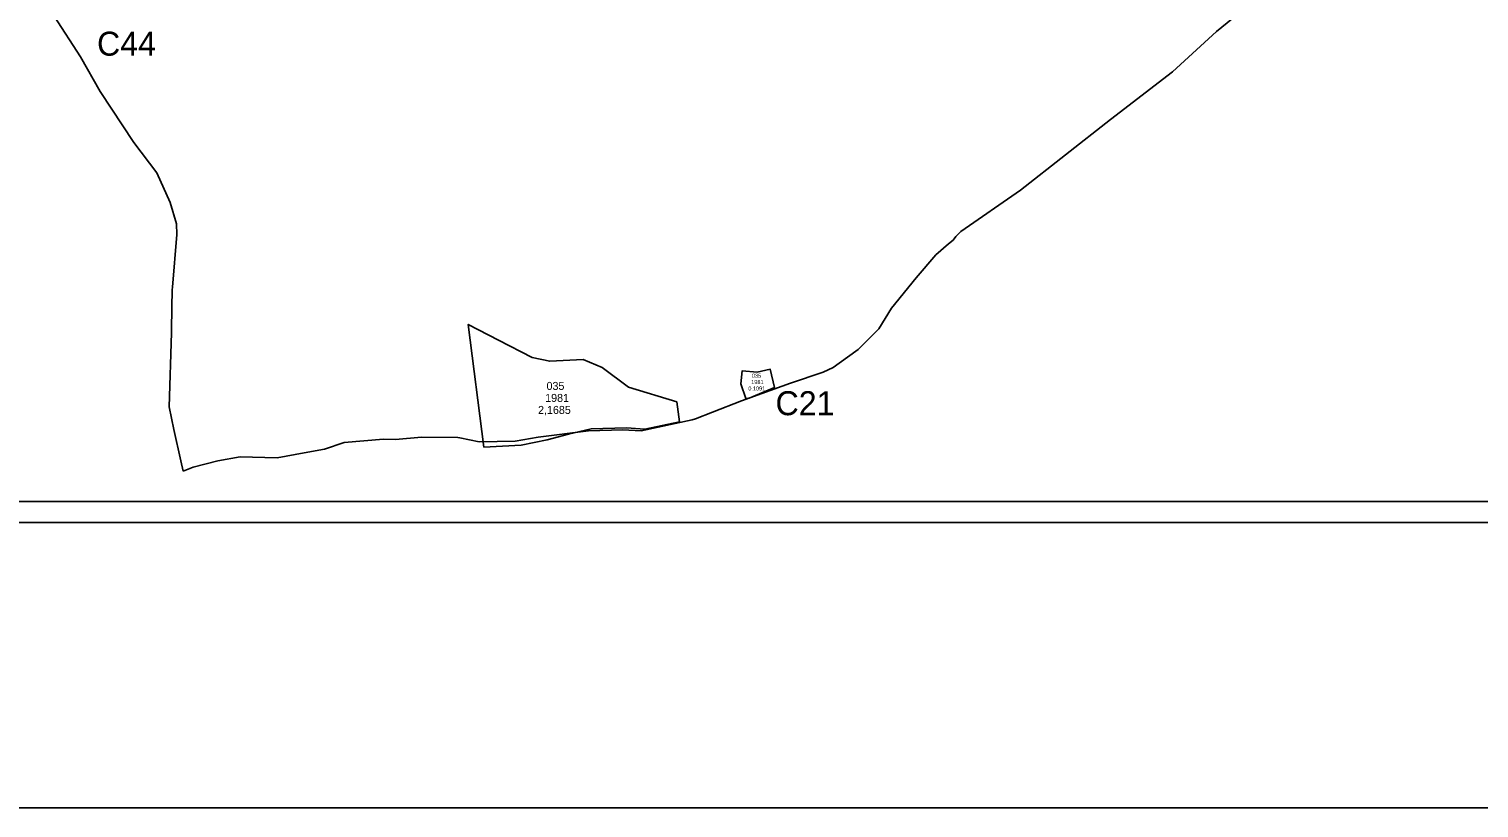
# Model space of a CAD drawing. Extents: x -557103 to -548162, y -1041918 to -1033974.
# Drawn here: x -554022 to -552210, y -1040019 to -1039045 of the extents above; entities that cross this region are included whole.
import ezdxf

# ---------------------------------------------------------------- set-up
doc = ezdxf.new("R2010")
doc.units = 0
for name, color, linetype in [('body1', 7, 'Continuous'), ('body3', 7, 'Continuous'), ('Rámeček', 7, 'Continuous'), ('Vrstva 37', 7, 'Continuous'), ('Vrstva 63', 7, 'Continuous'), ('Vrstva 9', 7, 'Continuous')]:
    doc.layers.add(name, color=color, linetype=linetype)

msp = doc.modelspace()

# ---------------------------------------------------------------- linework, layer by layer
at = {"layer": 'body1'}
msp.add_lwpolyline([(-550469.3, -1040018.6), (-555211.6, -1040018.6), (-555211.6, -1034654.7), (-550469.3, -1034654.7)], close=True, dxfattribs=at)
at = {"layer": 'body3'}
for p, q in [((-552537.9, -1039048.6), (-552497.9, -1039016.2)), ((-553990.6, -1039029.5), (-553957.8, -1039080.2)), ((-552593.2, -1039098.7), (-552537.9, -1039048.6)), ((-553957.8, -1039080.2), (-553932.9, -1039123.5)), ((-552670.5, -1039158.6), (-552593.2, -1039098.7)), ((-553932.9, -1039123.5), (-553891.2, -1039187.1)), ((-552783, -1039246.6), (-552670.5, -1039158.6)), ((-553891.2, -1039187.1), (-553862.3, -1039225.1)), ((-553862.3, -1039225.1), (-553845.6, -1039262.2)), ((-552857.7, -1039298.3), (-552783, -1039246.6)), ((-553845.6, -1039262.2), (-553837.6, -1039288.8)), ((-553837.6, -1039288.8), (-553837.4, -1039302.1)), ((-553837.4, -1039302.1), (-553842.9, -1039367.8)), ((-552873, -1039313.9), (-552867.3, -1039309.4)), ((-552867.3, -1039309.4), (-552863.8, -1039304.7)), ((-552863.8, -1039304.7), (-552857.7, -1039298.3)), ((-552913.4, -1039356.4), (-552888.8, -1039327.5)), ((-552888.8, -1039327.5), (-552873, -1039313.9)), ((-552944.4, -1039394.3), (-552913.4, -1039356.4)), ((-553843.4, -1039384.2), (-553843.6, -1039387.8)), ((-553843.1, -1039380.4), (-553843.4, -1039384.2)), ((-553842.9, -1039367.8), (-553843.2, -1039371.1)), ((-553843.2, -1039371.1), (-553843.2, -1039373.3)), ((-553843.2, -1039373.3), (-553843.1, -1039377.3)), ((-553843.1, -1039377.3), (-553843.1, -1039380.4)), ((-553843.7, -1039390.3), (-553844.1, -1039424.8)), ((-553843.6, -1039387.8), (-553843.7, -1039390.3)), ((-552960, -1039419.9), (-552944.4, -1039394.3)), ((-552985.9, -1039446), (-552960, -1039419.9)), ((-553844.1, -1039424.8), (-553846.8, -1039517.3)), ((-553017.3, -1039468.1), (-552999.4, -1039455.4)), ((-552999.4, -1039455.4), (-552985.9, -1039446)), ((-553070.4, -1039487.7), (-553029.7, -1039474.1)), ((-553029.7, -1039474.1), (-553017.3, -1039468.1)), ((-553131.7, -1039510.1), (-553070.4, -1039487.7)), ((-553167.7, -1039524.2), (-553131.7, -1039510.1)), ((-553846.8, -1039517.3), (-553841.1, -1039545.9)), ((-553189.2, -1039532.4), (-553167.7, -1039524.2)), ((-553841.1, -1039545.9), (-553832.2, -1039584.8)), ((-553385.8, -1039555.5), (-553322.8, -1039547.5)), ((-553322.8, -1039547.5), (-553279.9, -1039546.2)), ((-553279.9, -1039546.2), (-553257.2, -1039547.3)), ((-553257.2, -1039547.3), (-553193.2, -1039533.8)), ((-553193.2, -1039533.8), (-553189.2, -1039532.4)), ((-553652.8, -1039570.2), (-553628.1, -1039562.1)), ((-553628.1, -1039562.1), (-553579.1, -1039557.7)), ((-553579.1, -1039557.7), (-553564.1, -1039558.3)), ((-553564.1, -1039558.3), (-553531.4, -1039555.3)), ((-553531.4, -1039555.3), (-553486.2, -1039555.6)), ((-553486.2, -1039555.6), (-553483.7, -1039556.1)), ((-553483.7, -1039556.1), (-553459.3, -1039561)), ((-553459.3, -1039561), (-553414.7, -1039560.5)), ((-553414.7, -1039560.5), (-553385.8, -1039555.5)), ((-553785.9, -1039584.8), (-553758.1, -1039579.9)), ((-553758.1, -1039579.9), (-553712, -1039581.2)), ((-553712, -1039581.2), (-553678.2, -1039575)), ((-553678.2, -1039575), (-553652.8, -1039570.2)), ((-553832.2, -1039584.8), (-553829.3, -1039597.6)), ((-553829.3, -1039597.6), (-553817, -1039592.7)), ((-553817, -1039592.7), (-553785.9, -1039584.8))]:
    msp.add_line(p, q, dxfattribs=at)
at = {"layer": 'Rámeček'}
for points in [[(-555307.9, -1039662.1), (-550042, -1039662.1), (-550042, -1034604.4), (-555307.9, -1034604.4)], [(-555307.9, -1034604.4), (-548161.9, -1034604.4), (-548161.9, -1039661.8), (-555307.9, -1039661.8)]]:
    msp.add_lwpolyline(points, close=True, dxfattribs=at)
at = {"layer": 'Vrstva 63'}
msp.add_lwpolyline([(-550519.3, -1039635.9), (-556362.3, -1039635.9), (-556362.3, -1034682.3), (-550519.3, -1034682.3)], close=True, dxfattribs=at)
at = {"layer": 'Vrstva 9'}
for points in [[(-553453.8, -1039567.7), (-553473.1, -1039414.4), (-553435.4, -1039434.3), (-553393.4, -1039455.6), (-553371.2, -1039460.5), (-553329.6, -1039458.2), (-553305.7, -1039468.3), (-553272.8, -1039493), (-553212.5, -1039511.2), (-553209.3, -1039536.2), (-553252.5, -1039545.2), (-553275.5, -1039543.8), (-553319.5, -1039545), (-553348, -1039551.4), (-553374.6, -1039558.7), (-553407.2, -1039565.5)], [(-553126.2, -1039507), (-553132.7, -1039488.6), (-553130.7, -1039472.4), (-553112.1, -1039474.3), (-553095.8, -1039470.4), (-553090.4, -1039493.2), (-553122.2, -1039506.6)]]:
    msp.add_lwpolyline(points, close=True, dxfattribs=at)

# ---------------------------------------------------------------- texts
at = {"layer": 'Vrstva 37'}
for s, p in [('C44', (-553937, -1039078.7)), ('C21', (-553089.1, -1039527.9))]:
    msp.add_text(s, height=30, dxfattribs=at).set_placement(p)
at = {"layer": 'Vrstva 9'}
for s, height, p in [('035', 10, (-553375.3, -1039496.3)), ('0.1091', 5, (-553123.1, -1039497)), ('1981', 5, (-553119.5, -1039489)), ('035', 5, (-553118.6, -1039481)), ('1981', 10, (-553377, -1039511.3)), ('2,1685', 10, (-553385.9, -1039526.3))]:
    msp.add_text(s, height=height, dxfattribs=at).set_placement(p)

doc.saveas('drawing.dxf')
